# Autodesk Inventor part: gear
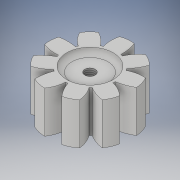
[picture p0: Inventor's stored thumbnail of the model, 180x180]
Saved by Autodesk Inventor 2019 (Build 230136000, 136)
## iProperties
Created: 2019-11
Part Number: gear
Material: Generic
Document SubType Name: Sheet Metal
Designer: PRADYUMNA
Density: 1 g/cm^3
Sheet Metal Rule: Default_mm
Appearance: Default
Author: PRADYUMNA
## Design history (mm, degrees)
sketch "Sketch1"
  geometry: C1 r 10 at (0, 0); 1 further point
  constraints: 1 centre point, 1 coincident
  dimensions: "d0" = 20 diameter of C1
extrude "Extrusion1" new body sketch "Sketch1" distance "d1" = 16; taper "d2" = 0 deg
sketch "Sketch2"
  geometry: A1 r 10 centre (0, 0) between (-9.723, -2.339) and (-9.292, 3.695) reference; A2 r 11.616 centre (-11.172, 9.187) between (-15.973, -1.391) and (-9.723, -2.339); A3 r 10.505 centre (-5.648, 0.543) between (-15.669, 3.695) and (-15.973, -1.391); A4 r 16.108 centre (-12.481, -12.095) between (-9.292, 3.695) and (-15.669, 3.695); 1 further point
  constraints: 8 point on circle, 3 centre point
extrude "Extrusion2" join sketch "Sketch2" distance "d3" = 16; taper "d4" = 0 deg
pattern_circular "Circular Pattern1" dims angle "d6" = 360 deg
sketch "Sketch3"
  geometry: C1 r 8.937 at (0, 0); 1 further point
  constraints: 1 centre point, 1 coincident
extrude "Extrusion3" cut sketch "Sketch3" distance "d8" = 2; taper "d9" = 0 deg
fillet "Fillet1" dims "d10" = 2
sketch "Sketch4"
  geometry: C1 r 2 at (0, 0); 1 further point
  constraints: 1 centre point, 1 coincident
  dimensions: "d11" = 4 diameter of C1
extrude "Extrusion4" cut sketch "Sketch4" distance "d12" = 16; taper "d13" = 0 deg
sketch "Sketch5"
  geometry: C1 r 8.937 at (0, 0); 1 further point
  constraints: 1 centre point, 1 coincident
extrude "Extrusion5" cut sketch "Sketch5" distance "d14" = 2; taper "d15" = 0 deg
fillet "Fillet2" dims "d16" = 2
thread "Thread1" dims "d17" = 10, "d18" = 0
body "Solid1"
other parameters: "Thickness" = 0.5, "BendRadius" = 0.5 (= Thickness), "BendReliefWidth" = 0.5 (= Thickness), "BendReliefDepth" = 0.25 (= 0.5 x Thickness), "CornerReliefSize" = 2 (= 4 x Thickness), "SeamGap" = 0.01, "MinimumRemnant" = 1 (= 2 x Thickness), "TransitionRadius" = 0.5 (= BendRadius), "JacobiRadiusSize" = 0.5 (= BendRadius), "GapSize" = 0.5 (= Thickness)
